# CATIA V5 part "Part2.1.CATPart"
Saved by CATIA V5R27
Part number: Part2_1
Bounding box of the stored display mesh (mm): x -35.74 to 35.74, y 5 to 19, z 232.868 to 304.132
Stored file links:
  E:\university\my-thesis\My Thesis Publication\Final-Updata\CAD\Part2.1.CATPart
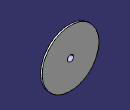
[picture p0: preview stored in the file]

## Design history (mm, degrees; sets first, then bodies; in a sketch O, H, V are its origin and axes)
Set1
  Plane1: type Offset, RefPlane DatumSurface1, Offset 2, reversed
  DatumSurface1
  Sketch1 on yz-plane, origin (0, 0, 0), H (0, 1, 0), V (0, 0, 1)
    line L1 (5, 268.5) -> (5, 266)
    line L2 (5, 266) -> (8, 266)
    line L3 (8, 266) -> (8, 253.5)
    point P4 (8, 253.5)
    line L4 (8, 253.5) -> (15, 250.75)
    line L5 (15, 250.75) -> (15, 238.75)
    line L6 (15, 238.75) -> (17, 238.75)
    line L7 (17, 238.75) -> (17, 232.75)
    line L8 (17, 232.75) -> (19, 232.75)
    line L9 (19, 232.75) -> (19, 268.5)
    line L10 (19, 268.5) -> (5, 268.5)
    projected line E1 (2, 267.5) -> (2, 269.5) from face of DatumSurface2
    projected line E2 (11, 269.5) -> (11, 267.5) from face of DatumSurface2
    point P14 (11, 267.5)
    reference intersected line E3 through (5, 0) direction (0, -1) from Plane1
    length L9 = 35.75
    length L7 = 6
    length L8 = 2
    length L6 = 2
    length L5 = 12
    distance L10 P4 = 15
    length L1 = 2.5
    length L10 = 14
    distance L1 E3 = 0
    distance L10 P14 = 1
    length L2 = 3
    vertical: L1 V, L3 V, L5 V, L7 V, L9 V
    horizontal: L2 H, L6 H, L8 H, L10 H
  DatumSurface2
Body1 (main body)
  Shaft1: profile Sketch1, axis Sketch1.L10, angle 360
  Sketch2 on face of Shaft1 from Sketch1.L9, origin (0, 19, 268.5), H (1, 0, 0), V (0, 0, -1)
    point P1 (0, 0)
  Hole1: placed by Sketch2, at (0, 19, 268.5) direction (0, -1, 0), diameter 8, depth 10, V-bottom angle 120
